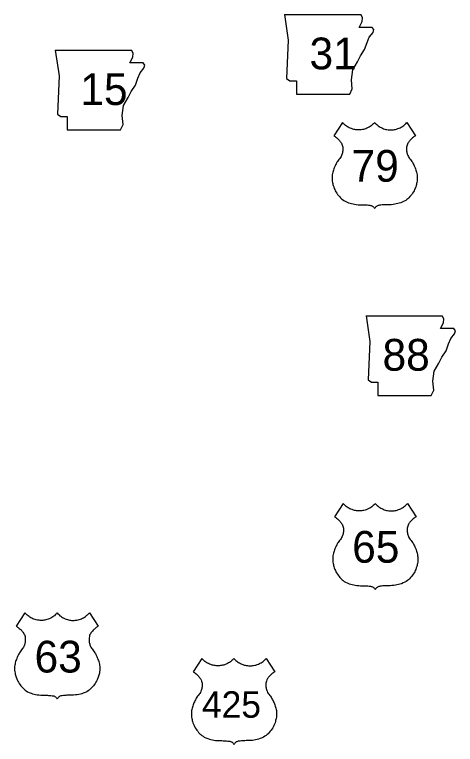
# Model space of a CAD drawing. Extents: x -819161 to 80911, y -6604 to 768454.
# Drawn here: x 45263 to 46143, y -6604 to -5148 of the extents above; entities that cross this region are included whole.
import ezdxf

# ---------------------------------------------------------------- set-up
doc = ezdxf.new("R2010")
doc.units = 0
doc.layers.add('21', color=7, linetype='Continuous')
doc.layers.add('22', color=7, linetype='Continuous')

msp = doc.modelspace()

# ---------------------------------------------------------------- linework, layer by layer
at = {"layer": '21'}
for p, q in [((45802.1, -5148.4), (45809.7, -5199.1)), ((45957.7, -5154.3), (45954.2, -5148.5)), ((45956.9, -5161.9), (45957.7, -5154.3)), ((45951, -5173.8), (45956.9, -5161.9)), ((45977.2, -5173.8), (45951, -5173.8)), ((45980.6, -5178), (45977.2, -5173.8)), ((45978.9, -5183.9), (45980.6, -5178)), ((45967, -5204.2), (45971.3, -5193.2)), ((45971.3, -5193.2), (45978.9, -5183.9)), ((45809.7, -5199.1), (45806.3, -5276.1)), ((45962, -5217.7), (45967, -5204.2)), ((45344.7, -5219.6), (45352.3, -5270.3)), ((45500.3, -5225.5), (45496.8, -5219.6)), ((45499.5, -5233.1), (45500.3, -5225.5)), ((45953.5, -5230.4), (45962, -5217.7)), ((45493.6, -5244.9), (45499.5, -5233.1)), ((45947.6, -5242.3), (45953.5, -5230.4)), ((45519.8, -5244.9), (45493.6, -5244.9)), ((45513.9, -5264.4), (45521.5, -5255.1)), ((45523.2, -5249.2), (45519.8, -5244.9)), ((45521.5, -5255.1), (45523.2, -5249.2)), ((45938.3, -5258.3), (45947.6, -5242.3)), ((45352.3, -5270.3), (45348.9, -5347.3)), ((45509.6, -5275.4), (45513.9, -5264.4)), ((45935.7, -5278.6), (45938.3, -5258.3)), ((45504.6, -5288.9), (45509.6, -5275.4)), ((45806.3, -5276.1), (45813.1, -5280.3)), ((45813.1, -5280.3), (45825.8, -5280.3)), ((45825.8, -5280.3), (45825.8, -5307.4)), ((45937.4, -5296.4), (45935.7, -5278.6)), ((45496.1, -5301.6), (45504.6, -5288.9)), ((45932.4, -5307.4), (45937.4, -5296.4)), ((45480.9, -5329.5), (45490.2, -5313.5)), ((45490.2, -5313.5), (45496.1, -5301.6)), ((45825.8, -5307.4), (45932.4, -5307.4)), ((45478.3, -5349.8), (45480.9, -5329.5)), ((45348.9, -5347.3), (45355.7, -5351.5)), ((45355.7, -5351.5), (45368.4, -5351.5)), ((45368.4, -5351.5), (45368.4, -5378.6)), ((45480, -5367.6), (45478.3, -5349.8)), ((45475, -5378.6), (45480, -5367.6)), ((45368.4, -5378.6), (45475, -5378.6)), ((45964.8, -5749.6), (45972.4, -5800.3)), ((46120.4, -5755.5), (46116.9, -5749.6)), ((46113.6, -5774.9), (46119.6, -5763.1)), ((46119.6, -5763.1), (46120.4, -5755.5)), ((46139.9, -5774.9), (46113.6, -5774.9)), ((46143.2, -5779.2), (46139.9, -5774.9)), ((46141.5, -5785.1), (46143.2, -5779.2)), ((46129.7, -5805.4), (46133.9, -5794.4)), ((46133.9, -5794.4), (46141.5, -5785.1)), ((45972.4, -5800.3), (45969, -5877.3)), ((46124.6, -5818.9), (46129.7, -5805.4)), ((46116.2, -5831.6), (46124.6, -5818.9)), ((46110.2, -5843.5), (46116.2, -5831.6)), ((46100.9, -5859.5), (46110.2, -5843.5)), ((46098.4, -5879.8), (46100.9, -5859.5)), ((45969, -5877.3), (45975.8, -5881.5)), ((45975.8, -5881.5), (45988.4, -5881.5)), ((45988.4, -5881.5), (45988.4, -5908.6)), ((46100.1, -5897.6), (46098.4, -5879.8)), ((45988.4, -5908.6), (46095, -5908.6)), ((46095, -5908.6), (46100.1, -5897.6))]:
    msp.add_line(p, q, dxfattribs=at)
for points in [[(45802.1, -5148.4), (45954.2, -5148.5)], [(45344.7, -5219.6), (45496.8, -5219.6)], [(45964.8, -5749.6), (46116.9, -5749.6)]]:
    msp.add_lwpolyline(points, dxfattribs=at)
at = {"layer": '22'}
for points in [[(45982.1, -5363.6), (45980.8, -5365.1), (45979.5, -5366.4), (45978.1, -5367.7), (45976.6, -5369), (45975.1, -5370.2), (45973.3, -5371.5), (45971.3, -5372.7), (45969.1, -5373.9), (45966.3, -5375.2), (45964.2, -5376), (45961.7, -5376.8), (45959.5, -5377.4), (45957.5, -5377.8), (45955.3, -5378.1), (45953.3, -5378.3), (45950.6, -5378.5), (45948.4, -5378.4), (45946.5, -5378.3), (45944.6, -5378.1), (45942.8, -5377.8), (45940.4, -5377.4), (45938.3, -5376.8), (45935.7, -5375.9), (45933.4, -5375.1), (45931.4, -5374.1), (45929.5, -5373.2), (45927.8, -5372.2), (45925.9, -5370.9), (45924.2, -5369.6), (45922.7, -5368.4), (45921.4, -5367.2), (45920.1, -5366), (45918.8, -5364.6), (45917.8, -5363.5), (45900.5, -5390.2), (45901.7, -5391), (45903.2, -5391.9), (45904.6, -5392.9), (45906.4, -5394.4), (45907.9, -5395.6), (45909.2, -5396.9), (45910.6, -5398.2), (45911.9, -5399.8), (45912.9, -5401), (45913.9, -5402.2), (45914.9, -5403.6), (45915.8, -5405), (45916.7, -5406.7), (45917.4, -5408.8), (45917.9, -5410.9), (45918.3, -5413.1), (45918.5, -5415.1), (45918.6, -5417.1), (45918.5, -5419), (45918.4, -5420.5), (45918.1, -5422.3), (45917.8, -5424), (45917.3, -5425.9), (45916.8, -5427.5), (45916.1, -5429.3), (45915, -5431.7), (45913.8, -5433.5), (45912.4, -5435.2), (45910.7, -5437.4), (45909.4, -5439.3), (45908.1, -5441.2), (45906.9, -5443.1), (45905.9, -5444.7), (45905, -5446.3), (45904.1, -5448.2), (45903, -5450.4), (45902.1, -5452.5), (45901.4, -5454.1), (45900.7, -5456.1), (45899.8, -5458.6), (45899.1, -5460.7), (45898.5, -5463), (45897.9, -5465.6), (45897.5, -5467.9), (45897.3, -5470.4), (45897.1, -5473), (45897.1, -5475.5), (45897.2, -5478), (45897.5, -5480.8), (45898, -5483.6), (45898.4, -5485.6), (45898.9, -5487.4), (45899.5, -5489.5), (45900.3, -5492), (45901.4, -5495.1), (45902.4, -5497.4), (45903.5, -5499.7), (45904.8, -5502), (45906.4, -5504.6), (45908.1, -5507), (45909.7, -5509.1), (45911.6, -5511.3), (45914, -5513.8), (45916, -5515.7), (45918.1, -5517.4)], [(45982.1, -5363.6), (45983.4, -5365.1), (45984.7, -5366.4), (45986.1, -5367.7), (45987.7, -5369), (45989.1, -5370.2), (45991, -5371.5), (45992.9, -5372.7), (45995.1, -5373.9), (45997.9, -5375.2), (46000, -5376), (46002.5, -5376.8), (46004.7, -5377.4), (46006.7, -5377.8), (46008.9, -5378.1), (46010.9, -5378.3), (46013.6, -5378.5), (46015.8, -5378.4), (46017.8, -5378.3), (46019.6, -5378.1), (46021.4, -5377.8), (46023.8, -5377.4), (46025.9, -5376.8), (46028.6, -5375.9), (46030.8, -5375.1), (46032.8, -5374.1), (46034.7, -5373.2), (46036.4, -5372.2), (46038.3, -5370.9), (46040.1, -5369.6), (46041.6, -5368.4), (46042.8, -5367.2), (46044.1, -5366), (46045.4, -5364.6), (46046.5, -5363.5), (46063.8, -5390.2), (46062.5, -5391), (46061.1, -5391.9), (46059.7, -5392.9), (46057.8, -5394.4), (46056.3, -5395.6), (46055, -5396.9), (46053.7, -5398.2), (46052.3, -5399.8), (46051.3, -5401), (46050.3, -5402.2), (46049.3, -5403.6), (46048.4, -5405), (46047.5, -5406.7), (46046.8, -5408.8), (46046.3, -5410.9), (46045.9, -5413.1), (46045.7, -5415.1), (46045.7, -5417.1), (46045.7, -5419), (46045.8, -5420.5), (46046.1, -5422.3), (46046.4, -5424), (46046.9, -5425.9), (46047.4, -5427.5), (46048.1, -5429.3), (46049.3, -5431.7), (46050.4, -5433.5), (46051.8, -5435.2), (46053.5, -5437.4), (46054.9, -5439.3), (46056.2, -5441.2), (46057.3, -5443.1), (46058.3, -5444.7), (46059.2, -5446.3), (46060.2, -5448.2), (46061.2, -5450.4), (46062.2, -5452.5), (46062.8, -5454.1), (46063.6, -5456.1), (46064.4, -5458.6), (46065.1, -5460.7), (46065.7, -5463), (46066.3, -5465.6), (46066.7, -5467.9), (46067, -5470.4), (46067.1, -5473), (46067.1, -5475.5), (46067, -5478), (46066.7, -5480.8), (46066.3, -5483.6), (46065.8, -5485.6), (46065.3, -5487.4), (46064.8, -5489.5), (46064, -5492), (46062.8, -5495.1), (46061.8, -5497.4), (46060.7, -5499.7), (46059.4, -5502), (46057.8, -5504.6), (46056.1, -5507), (46054.5, -5509.1), (46052.6, -5511.3), (46050.2, -5513.8), (46048.2, -5515.7), (46046.1, -5517.4)], [(45918.1, -5517.4), (45920.3, -5519), (45922.9, -5520.8), (45926.2, -5522.2), (45930, -5523.7), (45933.1, -5524.7), (45935.9, -5525.5), (45939.1, -5526.2), (45942.1, -5526.8), (45945.3, -5527.2), (45949.4, -5527.6), (45952.4, -5527.7), (45955.1, -5527.7), (45957.7, -5527.7), (45960.3, -5527.8), (45962.7, -5527.9), (45964.8, -5528), (45966.9, -5528.2), (45969.6, -5528.5), (45972.2, -5528.8), (45973.8, -5529), (45975.1, -5529.3), (45976.7, -5529.9), (45977.6, -5530.4), (45978.4, -5531), (45979.5, -5531.8), (45980.5, -5532.9), (45981.3, -5534), (45982.1, -5535.2)], [(46046.1, -5517.4), (46044, -5519), (46041.3, -5520.8), (46038.1, -5522.2), (46034.2, -5523.7), (46031.1, -5524.7), (46028.3, -5525.5), (46025.1, -5526.2), (46022.1, -5526.8), (46018.9, -5527.2), (46014.9, -5527.6), (46011.8, -5527.7), (46009.1, -5527.7), (46006.5, -5527.7), (46004, -5527.8), (46001.5, -5527.9), (45999.4, -5528), (45997.3, -5528.2), (45994.6, -5528.5), (45992, -5528.8), (45990.4, -5529), (45989.1, -5529.3), (45987.5, -5529.9), (45986.6, -5530.4), (45985.8, -5531), (45984.7, -5531.8), (45983.7, -5532.9), (45982.9, -5534), (45982.1, -5535.2)], [(45983.4, -6123.7), (45982.1, -6125.2), (45980.8, -6126.5), (45979.4, -6127.8), (45977.8, -6129.1), (45976.3, -6130.3), (45974.5, -6131.6), (45972.6, -6132.8), (45970.4, -6134), (45967.6, -6135.3), (45965.4, -6136.1), (45963, -6136.9), (45960.8, -6137.5), (45958.7, -6137.9), (45956.6, -6138.2), (45954.6, -6138.4), (45951.9, -6138.6), (45949.7, -6138.5), (45947.7, -6138.4), (45945.9, -6138.2), (45944.1, -6137.9), (45941.7, -6137.5), (45939.6, -6136.9), (45936.9, -6136), (45934.7, -6135.2), (45932.7, -6134.2), (45930.8, -6133.3), (45929.1, -6132.3), (45927.2, -6131), (45925.4, -6129.7), (45923.9, -6128.5), (45922.6, -6127.3), (45921.3, -6126.1), (45920.1, -6124.7), (45919, -6123.6), (45901.7, -6150.3), (45903, -6151.1), (45904.4, -6152), (45905.8, -6153), (45907.7, -6154.5), (45909.2, -6155.7), (45910.5, -6157), (45911.8, -6158.3), (45913.2, -6159.9), (45914.2, -6161), (45915.2, -6162.3), (45916.1, -6163.7), (45917.1, -6165.1), (45918, -6166.8), (45918.7, -6168.9), (45919.2, -6171), (45919.6, -6173.2), (45919.8, -6175.2), (45919.8, -6177.2), (45919.8, -6179.1), (45919.7, -6180.6), (45919.4, -6182.4), (45919.1, -6184.1), (45918.6, -6186), (45918.1, -6187.6), (45917.4, -6189.4), (45916.2, -6191.8), (45915.1, -6193.6), (45913.7, -6195.3), (45912, -6197.5), (45910.6, -6199.4), (45909.3, -6201.3), (45908.2, -6203.2), (45907.2, -6204.8), (45906.3, -6206.4), (45905.3, -6208.3), (45904.3, -6210.5), (45903.3, -6212.6), (45902.7, -6214.2), (45901.9, -6216.2), (45901.1, -6218.7), (45900.4, -6220.8), (45899.8, -6223.1), (45899.2, -6225.7), (45898.8, -6228), (45898.5, -6230.5), (45898.4, -6233.1), (45898.4, -6235.6), (45898.5, -6238.1), (45898.8, -6240.9), (45899.2, -6243.7), (45899.7, -6245.7), (45900.1, -6247.5), (45900.7, -6249.6), (45901.5, -6252.1), (45902.7, -6255.2), (45903.7, -6257.5), (45904.8, -6259.8), (45906.1, -6262.1), (45907.7, -6264.7), (45909.4, -6267.1), (45911, -6269.2), (45912.9, -6271.4), (45915.2, -6273.9), (45917.3, -6275.8), (45919.4, -6277.5)], [(45983.4, -6123.7), (45984.7, -6125.2), (45986, -6126.5), (45987.4, -6127.8), (45988.9, -6129.1), (45990.4, -6130.3), (45992.2, -6131.6), (45994.2, -6132.8), (45996.4, -6134), (45999.2, -6135.3), (46001.3, -6136.1), (46003.7, -6136.9), (46006, -6137.5), (46008, -6137.9), (46010.2, -6138.2), (46012.2, -6138.4), (46014.9, -6138.6), (46017.1, -6138.5), (46019, -6138.4), (46020.9, -6138.2), (46022.7, -6137.9), (46025, -6137.5), (46027.2, -6136.9), (46029.8, -6136), (46032.1, -6135.2), (46034.1, -6134.2), (46035.9, -6133.3), (46037.7, -6132.3), (46039.6, -6131), (46041.3, -6129.7), (46042.8, -6128.5), (46044.1, -6127.3), (46045.4, -6126.1), (46046.7, -6124.7), (46047.7, -6123.6), (46065, -6150.3), (46063.8, -6151.1), (46062.3, -6152), (46060.9, -6153), (46059.1, -6154.5), (46057.6, -6155.7), (46056.3, -6157), (46054.9, -6158.3), (46053.6, -6159.9), (46052.6, -6161), (46051.6, -6162.3), (46050.6, -6163.7), (46049.7, -6165.1), (46048.8, -6166.8), (46048.1, -6168.9), (46047.6, -6171), (46047.2, -6173.2), (46047, -6175.2), (46046.9, -6177.2), (46047, -6179.1), (46047.1, -6180.6), (46047.4, -6182.4), (46047.7, -6184.1), (46048.2, -6186), (46048.7, -6187.6), (46049.4, -6189.4), (46050.5, -6191.8), (46051.7, -6193.6), (46053.1, -6195.3), (46054.8, -6197.5), (46056.1, -6199.4), (46057.4, -6201.3), (46058.6, -6203.2), (46059.6, -6204.8), (46060.5, -6206.4), (46061.4, -6208.3), (46062.5, -6210.5), (46063.4, -6212.6), (46064.1, -6214.2), (46064.8, -6216.2), (46065.7, -6218.7), (46066.3, -6220.8), (46067, -6223.1), (46067.6, -6225.7), (46067.9, -6228), (46068.2, -6230.5), (46068.4, -6233.1), (46068.4, -6235.6), (46068.3, -6238.1), (46068, -6240.9), (46067.5, -6243.7), (46067.1, -6245.7), (46066.6, -6247.5), (46066, -6249.6), (46065.2, -6252.1), (46064.1, -6255.2), (46063.1, -6257.5), (46062, -6259.8), (46060.7, -6262.1), (46059.1, -6264.7), (46057.4, -6267.1), (46055.8, -6269.2), (46053.9, -6271.4), (46051.5, -6273.9), (46049.5, -6275.8), (46047.4, -6277.5)], [(45919.4, -6277.5), (45921.5, -6279.1), (45924.1, -6280.8), (45927.4, -6282.3), (45931.3, -6283.8), (45934.4, -6284.8), (45937.2, -6285.6), (45940.4, -6286.3), (45943.4, -6286.9), (45946.6, -6287.3), (45950.6, -6287.7), (45953.7, -6287.8), (45956.4, -6287.8), (45958.9, -6287.8), (45961.5, -6287.9), (45964, -6288), (45966.1, -6288.1), (45968.2, -6288.3), (45970.9, -6288.6), (45973.5, -6288.9), (45975.1, -6289.1), (45976.4, -6289.4), (45978, -6290), (45978.9, -6290.5), (45979.7, -6291.1), (45980.7, -6291.9), (45981.8, -6293), (45982.6, -6294.1), (45983.4, -6295.3)], [(46047.4, -6277.5), (46045.2, -6279.1), (46042.6, -6280.8), (46039.3, -6282.3), (46035.5, -6283.8), (46032.4, -6284.8), (46029.6, -6285.6), (46026.4, -6286.3), (46023.4, -6286.9), (46020.2, -6287.3), (46016.1, -6287.7), (46013, -6287.8), (46010.4, -6287.8), (46007.8, -6287.8), (46005.2, -6287.9), (46002.8, -6288), (46000.7, -6288.1), (45998.6, -6288.3), (45995.9, -6288.6), (45993.2, -6288.9), (45991.7, -6289.1), (45990.4, -6289.4), (45988.8, -6290), (45987.9, -6290.5), (45987.1, -6291.1), (45986, -6291.9), (45985, -6293), (45984.1, -6294.1), (45983.4, -6295.3)], [(45348.5, -6342.1), (45347.2, -6343.6), (45345.9, -6344.9), (45344.5, -6346.2), (45342.9, -6347.6), (45341.4, -6348.7), (45339.6, -6350), (45337.7, -6351.2), (45335.5, -6352.4), (45332.7, -6353.7), (45330.5, -6354.5), (45328.1, -6355.3), (45325.9, -6355.9), (45323.8, -6356.3), (45321.7, -6356.7), (45319.7, -6356.9), (45317, -6357), (45314.8, -6357), (45312.8, -6356.8), (45311, -6356.6), (45309.1, -6356.4), (45306.8, -6355.9), (45304.7, -6355.3), (45302, -6354.5), (45299.8, -6353.6), (45297.8, -6352.7), (45295.9, -6351.7), (45294.2, -6350.7), (45292.3, -6349.4), (45290.5, -6348.1), (45289, -6346.9), (45287.7, -6345.8), (45286.4, -6344.5), (45285.2, -6343.2), (45284.1, -6342), (45266.8, -6368.8), (45268.1, -6369.5), (45269.5, -6370.5), (45270.9, -6371.4), (45272.8, -6372.9), (45274.3, -6374.2), (45275.6, -6375.4), (45276.9, -6376.8), (45278.3, -6378.3), (45279.3, -6379.5), (45280.3, -6380.7), (45281.2, -6382.1), (45282.2, -6383.6), (45283.1, -6385.3), (45283.8, -6387.3), (45284.3, -6389.4), (45284.6, -6391.6), (45284.9, -6393.7), (45284.9, -6395.7), (45284.9, -6397.5), (45284.8, -6399), (45284.5, -6400.8), (45284.2, -6402.5), (45283.7, -6404.4), (45283.2, -6406), (45282.5, -6407.8), (45281.3, -6410.2), (45280.2, -6412.1), (45278.8, -6413.7), (45277.1, -6415.9), (45275.7, -6417.8), (45274.4, -6419.7), (45273.3, -6421.6), (45272.3, -6423.3), (45271.4, -6424.8), (45270.4, -6426.7), (45269.4, -6428.9), (45268.4, -6431), (45267.8, -6432.6), (45267, -6434.7), (45266.2, -6437.1), (45265.5, -6439.2), (45264.9, -6441.5), (45264.3, -6444.1), (45263.9, -6446.4), (45263.6, -6448.9), (45263.5, -6451.5), (45263.5, -6454), (45263.6, -6456.5), (45263.9, -6459.4), (45264.3, -6462.1), (45264.8, -6464.2), (45265.2, -6466), (45265.8, -6468), (45266.6, -6470.5), (45267.8, -6473.6), (45268.8, -6475.9), (45269.9, -6478.2), (45271.2, -6480.5), (45272.8, -6483.1), (45274.5, -6485.6), (45276.1, -6487.7), (45277.9, -6489.8), (45280.3, -6492.3), (45282.4, -6494.2), (45284.5, -6495.9)], [(45348.5, -6342.1), (45349.8, -6343.6), (45351, -6344.9), (45352.5, -6346.2), (45354, -6347.6), (45355.5, -6348.7), (45357.3, -6350), (45359.3, -6351.2), (45361.5, -6352.4), (45364.3, -6353.7), (45366.4, -6354.5), (45368.8, -6355.3), (45371.1, -6355.9), (45373.1, -6356.3), (45375.3, -6356.7), (45377.3, -6356.9), (45380, -6357), (45382.2, -6357), (45384.1, -6356.8), (45385.9, -6356.6), (45387.8, -6356.4), (45390.1, -6355.9), (45392.3, -6355.3), (45394.9, -6354.5), (45397.2, -6353.6), (45399.2, -6352.7), (45401, -6351.7), (45402.8, -6350.7), (45404.7, -6349.4), (45406.4, -6348.1), (45407.9, -6346.9), (45409.2, -6345.8), (45410.5, -6344.5), (45411.8, -6343.2), (45412.8, -6342), (45430.1, -6368.8), (45428.9, -6369.5), (45427.4, -6370.5), (45426, -6371.4), (45424.2, -6372.9), (45422.7, -6374.2), (45421.4, -6375.4), (45420, -6376.8), (45418.7, -6378.3), (45417.7, -6379.5), (45416.7, -6380.7), (45415.7, -6382.1), (45414.8, -6383.6), (45413.9, -6385.3), (45413.2, -6387.3), (45412.7, -6389.4), (45412.3, -6391.6), (45412.1, -6393.7), (45412, -6395.7), (45412.1, -6397.5), (45412.2, -6399), (45412.4, -6400.8), (45412.8, -6402.5), (45413.3, -6404.4), (45413.8, -6406), (45414.5, -6407.8), (45415.6, -6410.2), (45416.8, -6412.1), (45418.2, -6413.7), (45419.9, -6415.9), (45421.2, -6417.8), (45422.5, -6419.7), (45423.7, -6421.6), (45424.7, -6423.3), (45425.6, -6424.8), (45426.5, -6426.7), (45427.6, -6428.9), (45428.5, -6431), (45429.2, -6432.6), (45429.9, -6434.7), (45430.8, -6437.1), (45431.4, -6439.2), (45432.1, -6441.5), (45432.7, -6444.1), (45433, -6446.4), (45433.3, -6448.9), (45433.5, -6451.5), (45433.5, -6454), (45433.4, -6456.5), (45433.1, -6459.4), (45432.6, -6462.1), (45432.2, -6464.2), (45431.7, -6466), (45431.1, -6468), (45430.3, -6470.5), (45429.2, -6473.6), (45428.2, -6475.9), (45427.1, -6478.2), (45425.8, -6480.5), (45424.2, -6483.1), (45422.5, -6485.6), (45420.9, -6487.7), (45419, -6489.8), (45416.6, -6492.3), (45414.6, -6494.2), (45412.5, -6495.9)], [(45701.3, -6432.8), (45700, -6434.3), (45698.7, -6435.6), (45697.3, -6436.9), (45695.8, -6438.2), (45694.3, -6439.4), (45692.5, -6440.7), (45690.5, -6441.9), (45688.3, -6443.1), (45685.5, -6444.4), (45683.4, -6445.2), (45680.9, -6446), (45678.7, -6446.6), (45676.7, -6447), (45674.5, -6447.3), (45672.5, -6447.5), (45669.8, -6447.7), (45667.6, -6447.6), (45665.7, -6447.5), (45663.8, -6447.3), (45662, -6447.1), (45659.6, -6446.6), (45657.5, -6446), (45654.8, -6445.2), (45652.6, -6444.3), (45650.6, -6443.3), (45648.7, -6442.4), (45647, -6441.4), (45645.1, -6440.1), (45643.4, -6438.8), (45641.8, -6437.6), (45640.6, -6436.5), (45639.3, -6435.2), (45638, -6433.9), (45637, -6432.7), (45619.7, -6459.4), (45620.9, -6460.2), (45622.4, -6461.1), (45623.8, -6462.1), (45625.6, -6463.6), (45627.1, -6464.9), (45628.4, -6466.1), (45629.8, -6467.4), (45631.1, -6469), (45632.1, -6470.2), (45633.1, -6471.4), (45634.1, -6472.8), (45635, -6474.2), (45635.9, -6475.9), (45636.6, -6478), (45637.1, -6480.1), (45637.5, -6482.3), (45637.7, -6484.4), (45637.8, -6486.3), (45637.7, -6488.2), (45637.6, -6489.7), (45637.3, -6491.5), (45637, -6493.2), (45636.5, -6495.1), (45636, -6496.7), (45635.3, -6498.5), (45634.2, -6500.9), (45633, -6502.7), (45631.6, -6504.4), (45629.9, -6506.6), (45628.5, -6508.5), (45627.3, -6510.4), (45626.1, -6512.3), (45625.1, -6513.9), (45624.2, -6515.5), (45623.3, -6517.4), (45622.2, -6519.6), (45621.3, -6521.7), (45620.6, -6523.3), (45619.9, -6525.3), (45619, -6527.8), (45618.3, -6529.9), (45617.7, -6532.2), (45617.1, -6534.8), (45616.7, -6537.1), (45616.5, -6539.6), (45616.3, -6542.2), (45616.3, -6544.7), (45616.4, -6547.2), (45616.7, -6550.1), (45617.2, -6552.8), (45617.6, -6554.8), (45618.1, -6556.6), (45618.7, -6558.7), (45619.5, -6561.2), (45620.6, -6564.3), (45621.6, -6566.6), (45622.7, -6568.9), (45624, -6571.2), (45625.6, -6573.8), (45627.3, -6576.2), (45628.9, -6578.3), (45630.8, -6580.5), (45633.2, -6583), (45635.2, -6584.9), (45637.3, -6586.6)], [(45701.3, -6432.8), (45702.6, -6434.3), (45703.9, -6435.6), (45705.3, -6436.9), (45706.9, -6438.2), (45708.3, -6439.4), (45710.1, -6440.7), (45712.1, -6441.9), (45714.3, -6443.1), (45717.1, -6444.4), (45719.2, -6445.2), (45721.7, -6446), (45723.9, -6446.6), (45725.9, -6447), (45728.1, -6447.3), (45730.1, -6447.5), (45732.8, -6447.7), (45735, -6447.6), (45736.9, -6447.5), (45738.8, -6447.3), (45740.6, -6447.1), (45743, -6446.6), (45745.1, -6446), (45747.8, -6445.2), (45750, -6444.3), (45752, -6443.3), (45753.9, -6442.4), (45755.6, -6441.4), (45757.5, -6440.1), (45759.3, -6438.8), (45760.8, -6437.6), (45762, -6436.5), (45763.3, -6435.2), (45764.6, -6433.9), (45765.7, -6432.7), (45783, -6459.4), (45781.7, -6460.2), (45780.3, -6461.1), (45778.9, -6462.1), (45777, -6463.6), (45775.5, -6464.9), (45774.2, -6466.1), (45772.9, -6467.4), (45771.5, -6469), (45770.5, -6470.2), (45769.5, -6471.4), (45768.5, -6472.8), (45767.6, -6474.2), (45766.7, -6475.9), (45766, -6478), (45765.5, -6480.1), (45765.1, -6482.3), (45764.9, -6484.4), (45764.9, -6486.3), (45764.9, -6488.2), (45765, -6489.7), (45765.3, -6491.5), (45765.6, -6493.2), (45766.1, -6495.1), (45766.6, -6496.7), (45767.3, -6498.5), (45768.5, -6500.9), (45769.6, -6502.7), (45771, -6504.4), (45772.7, -6506.6), (45774.1, -6508.5), (45775.4, -6510.4), (45776.5, -6512.3), (45777.5, -6513.9), (45778.4, -6515.5), (45779.4, -6517.4), (45780.4, -6519.6), (45781.3, -6521.7), (45782, -6523.3), (45782.8, -6525.3), (45783.6, -6527.8), (45784.3, -6529.9), (45784.9, -6532.2), (45785.5, -6534.8), (45785.9, -6537.1), (45786.1, -6539.6), (45786.3, -6542.2), (45786.3, -6544.7), (45786.2, -6547.2), (45785.9, -6550.1), (45785.5, -6552.8), (45785, -6554.8), (45784.5, -6556.6), (45784, -6558.7), (45783.2, -6561.2), (45782, -6564.3), (45781, -6566.6), (45779.9, -6568.9), (45778.6, -6571.2), (45777, -6573.8), (45775.3, -6576.2), (45773.7, -6578.3), (45771.8, -6580.5), (45769.4, -6583), (45767.4, -6584.9), (45765.3, -6586.6)], [(45284.5, -6495.9), (45286.6, -6497.6), (45289.2, -6499.3), (45292.5, -6500.7), (45296.3, -6502.2), (45299.5, -6503.2), (45302.3, -6504), (45305.5, -6504.7), (45308.5, -6505.3), (45311.7, -6505.7), (45315.7, -6506.1), (45318.8, -6506.2), (45321.5, -6506.2), (45324, -6506.2), (45326.6, -6506.3), (45329.1, -6506.4), (45331.2, -6506.6), (45333.3, -6506.7), (45336, -6507), (45338.6, -6507.3), (45340.2, -6507.6), (45341.5, -6507.8), (45343.1, -6508.5), (45344, -6509), (45344.8, -6509.5), (45345.8, -6510.4), (45346.9, -6511.4), (45347.7, -6512.5), (45348.5, -6513.7)], [(45412.5, -6495.9), (45410.3, -6497.6), (45407.7, -6499.3), (45404.4, -6500.7), (45400.6, -6502.2), (45397.5, -6503.2), (45394.7, -6504), (45391.5, -6504.7), (45388.5, -6505.3), (45385.3, -6505.7), (45381.2, -6506.1), (45378.1, -6506.2), (45375.5, -6506.2), (45372.9, -6506.2), (45370.3, -6506.3), (45367.9, -6506.4), (45365.8, -6506.6), (45363.7, -6506.7), (45361, -6507), (45358.3, -6507.3), (45356.8, -6507.6), (45355.5, -6507.8), (45353.9, -6508.5), (45353, -6509), (45352.2, -6509.5), (45351.1, -6510.4), (45350.1, -6511.4), (45349.2, -6512.5), (45348.5, -6513.7)], [(45637.3, -6586.6), (45639.5, -6588.3), (45642.1, -6590), (45645.3, -6591.4), (45649.2, -6592.9), (45652.3, -6593.9), (45655.1, -6594.7), (45658.3, -6595.4), (45661.3, -6596), (45664.5, -6596.4), (45668.5, -6596.8), (45671.6, -6596.9), (45674.3, -6596.9), (45676.9, -6596.9), (45679.5, -6597), (45681.9, -6597.1), (45684, -6597.2), (45686.1, -6597.4), (45688.8, -6597.7), (45691.4, -6598), (45693, -6598.2), (45694.3, -6598.5), (45695.9, -6599.1), (45696.8, -6599.6), (45697.6, -6600.2), (45698.7, -6601), (45699.7, -6602.1), (45700.5, -6603.2), (45701.3, -6604.4)], [(45765.3, -6586.6), (45763.2, -6588.3), (45760.5, -6590), (45757.3, -6591.4), (45753.4, -6592.9), (45750.3, -6593.9), (45747.5, -6594.7), (45744.3, -6595.4), (45741.3, -6596), (45738.1, -6596.4), (45734.1, -6596.8), (45731, -6596.9), (45728.3, -6596.9), (45725.7, -6596.9), (45723.2, -6597), (45720.7, -6597.1), (45718.6, -6597.2), (45716.5, -6597.4), (45713.8, -6597.7), (45711.2, -6598), (45709.6, -6598.2), (45708.3, -6598.5), (45706.7, -6599.1), (45705.8, -6599.6), (45705, -6600.2), (45703.9, -6601), (45702.9, -6602.1), (45702.1, -6603.2), (45701.3, -6604.4)]]:
    msp.add_lwpolyline(points, dxfattribs=at)

# ---------------------------------------------------------------- texts
at = {"layer": '21'}
for s, p in [('31', (45852.1, -5257.6)), ('15', (45394.7, -5328.8)), ('88', (45997.8, -5858.8))]:
    msp.add_text(s, height=63.36, dxfattribs=at).set_placement(p)
at = {"layer": '22'}
for s, height, p in [('79', 63.36, (45936, -5481.8)), ('65', 63.36, (45937.2, -6241.9)), ('63', 63.36, (45303.3, -6461)), ('425', 52.8, (45637.4, -6551.2))]:
    msp.add_text(s, height=height, dxfattribs=at).set_placement(p)

doc.saveas('drawing.dxf')
